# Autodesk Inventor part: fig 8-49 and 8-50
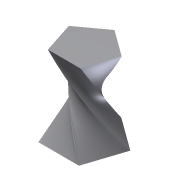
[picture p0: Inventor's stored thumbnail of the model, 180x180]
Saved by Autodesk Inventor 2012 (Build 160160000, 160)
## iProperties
Shininess: 64.0
Length Units: 11269
Angle Units: 11279
Time Units: 11290
Mass Units: 11283
Length Display Precision: 3
Angle Display Precision: 2
Compacted: True
Part Number: fig 8-49 and 8-50
Document SubType Name: Modeling
Created: 2002-12
Designer: deepak
Density: 1 g/cm^3
Material: Default
Density: 0.0
Volumn: 0.0
Area: 0.0
PropertySet Name: Model Information
Control State: 0
Master: False
Checked Out: False
Author: deepak
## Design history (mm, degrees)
sketch "Sketch1"
  geometry: L1 (0, 21.819)-(20.751, 6.743); L2 (20.751, 6.743)-(12.825, -17.652); L3 (12.825, -17.652)-(-12.825, -17.652); L4 (-12.825, -17.652)-(-20.751, 6.743); L5 (-20.751, 6.743)-(0, 21.819); 1 further point
  constraints: 10 end point, 9 other
workplane "Work Plane1"
sketch "Sketch2"
  geometry: L1 (0, 8.24)-(7.836, 2.546); L2 (7.836, 2.546)-(4.843, -6.666); L3 (4.843, -6.666)-(-4.843, -6.666); L4 (-4.843, -6.666)-(-7.836, 2.546); L5 (-7.836, 2.546)-(0, 8.24); 1 further point
  constraints: 10 end point, 9 other
workplane "Work Plane2"
sketch "Sketch3"
  geometry: L1 (0, 17.494)-(16.637, 5.406); L2 (16.637, 5.406)-(10.283, -14.153); L3 (10.283, -14.153)-(-10.283, -14.153); L4 (-10.283, -14.153)-(-16.637, 5.406); L5 (-16.637, 5.406)-(0, 17.494); 1 further point
  constraints: 10 end point, 9 other
loft "Loft4" sketch "Sketch3" dims "d20" = 0, "d21" = 90 deg, "d22" = 0, "d23" = 90 deg, "d24" = 0, "d25" = 90 deg
body "Solid1"
other parameters: "d0" = 25, "d1" = 25
